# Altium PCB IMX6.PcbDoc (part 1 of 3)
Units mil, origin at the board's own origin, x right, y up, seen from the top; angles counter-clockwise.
Board outline 7950 x 5550 mil, 4 copper layers (Top Layer, GND, VCC, Bottom Layer), stack 30.634 mil thick; 238 components, 319 nets, 1015 pads, 404 vias.
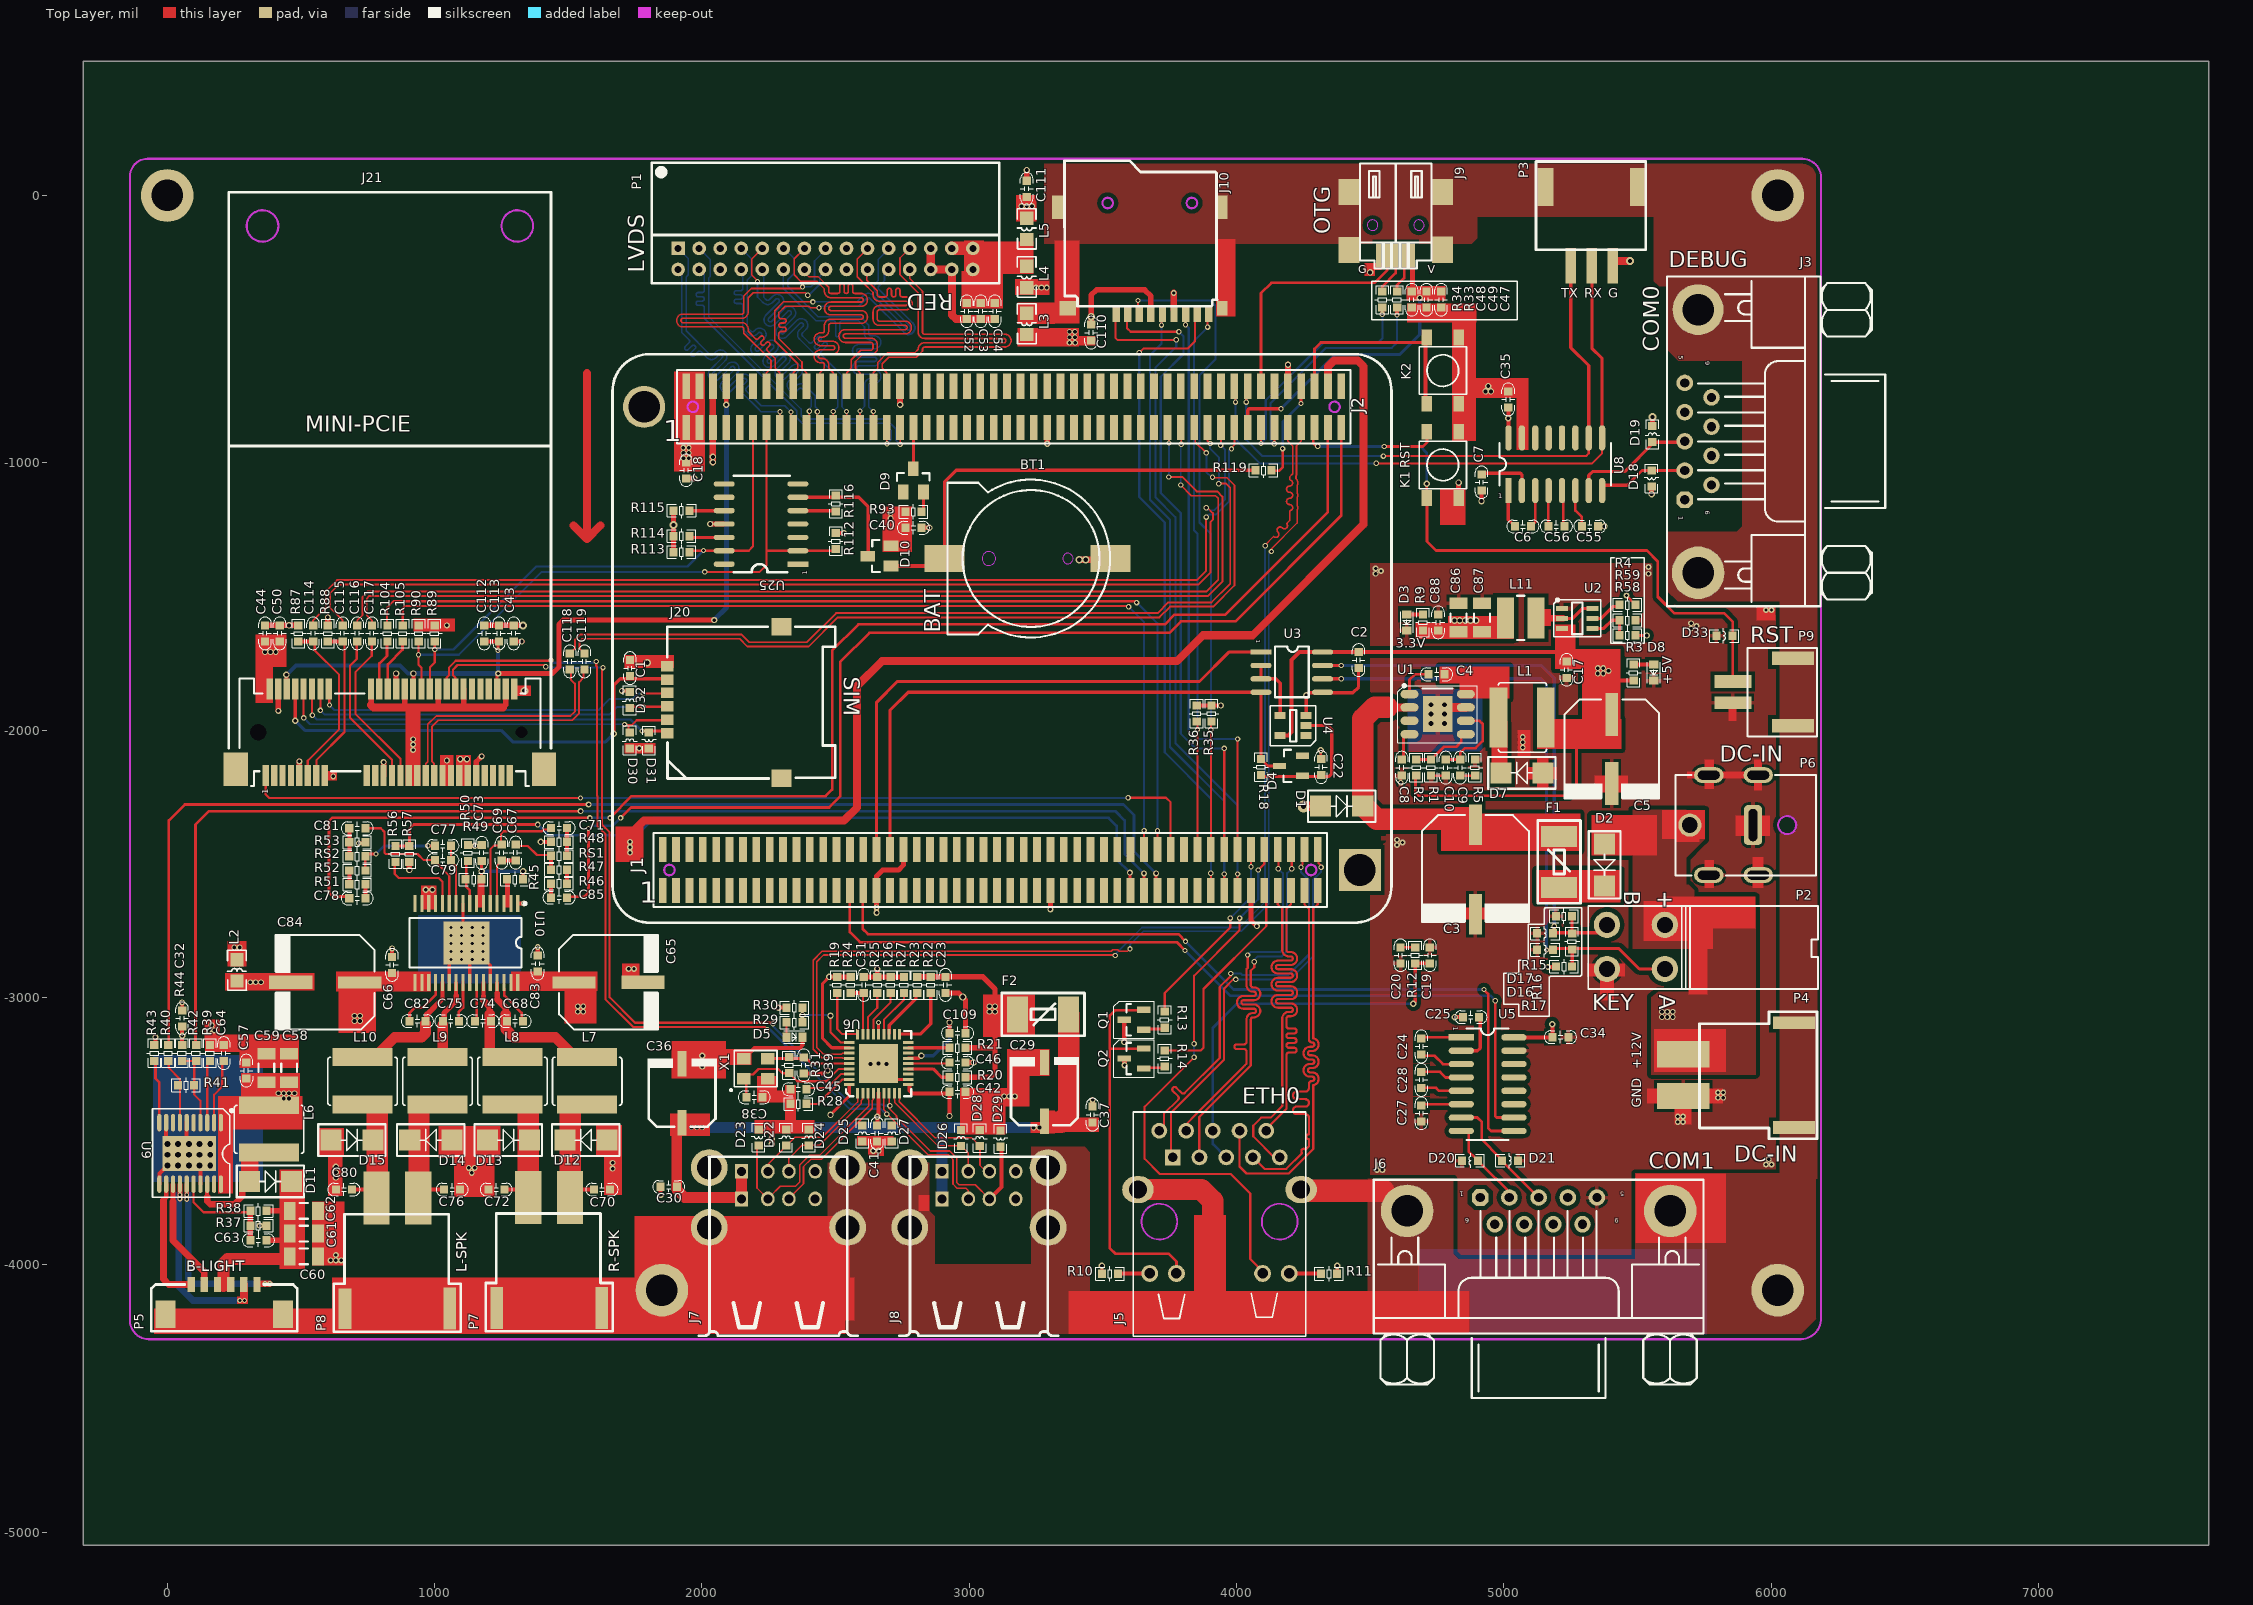
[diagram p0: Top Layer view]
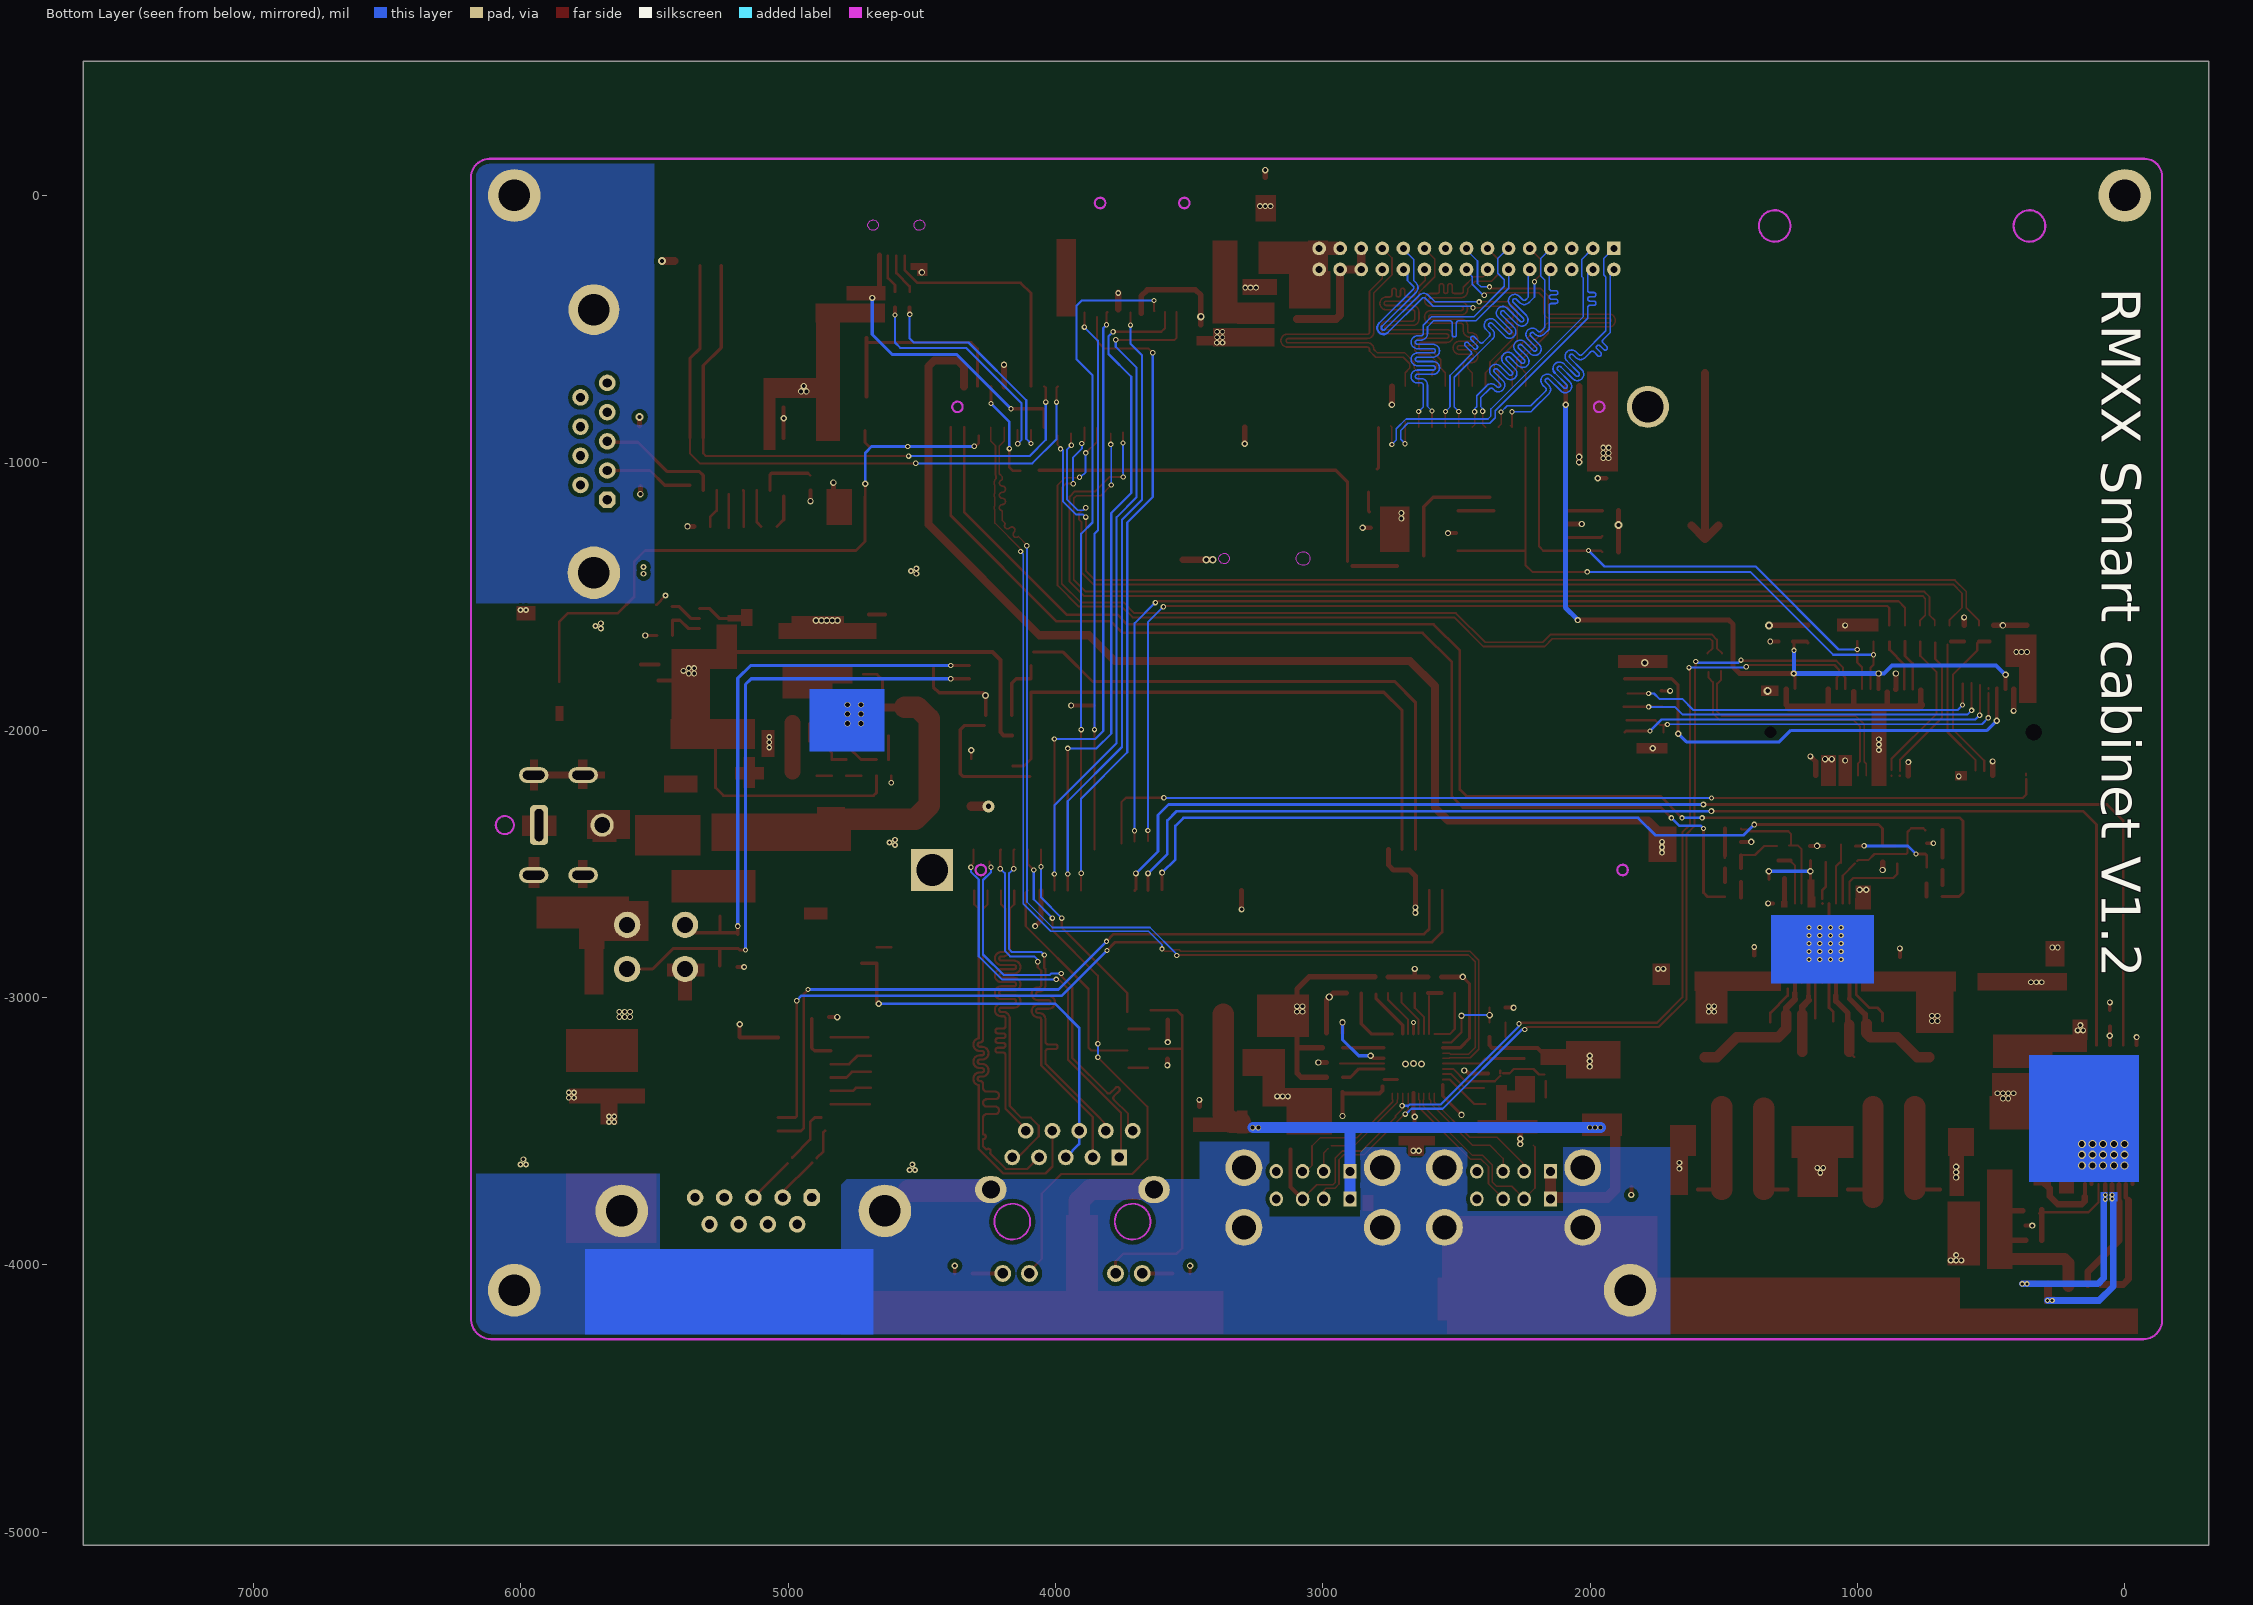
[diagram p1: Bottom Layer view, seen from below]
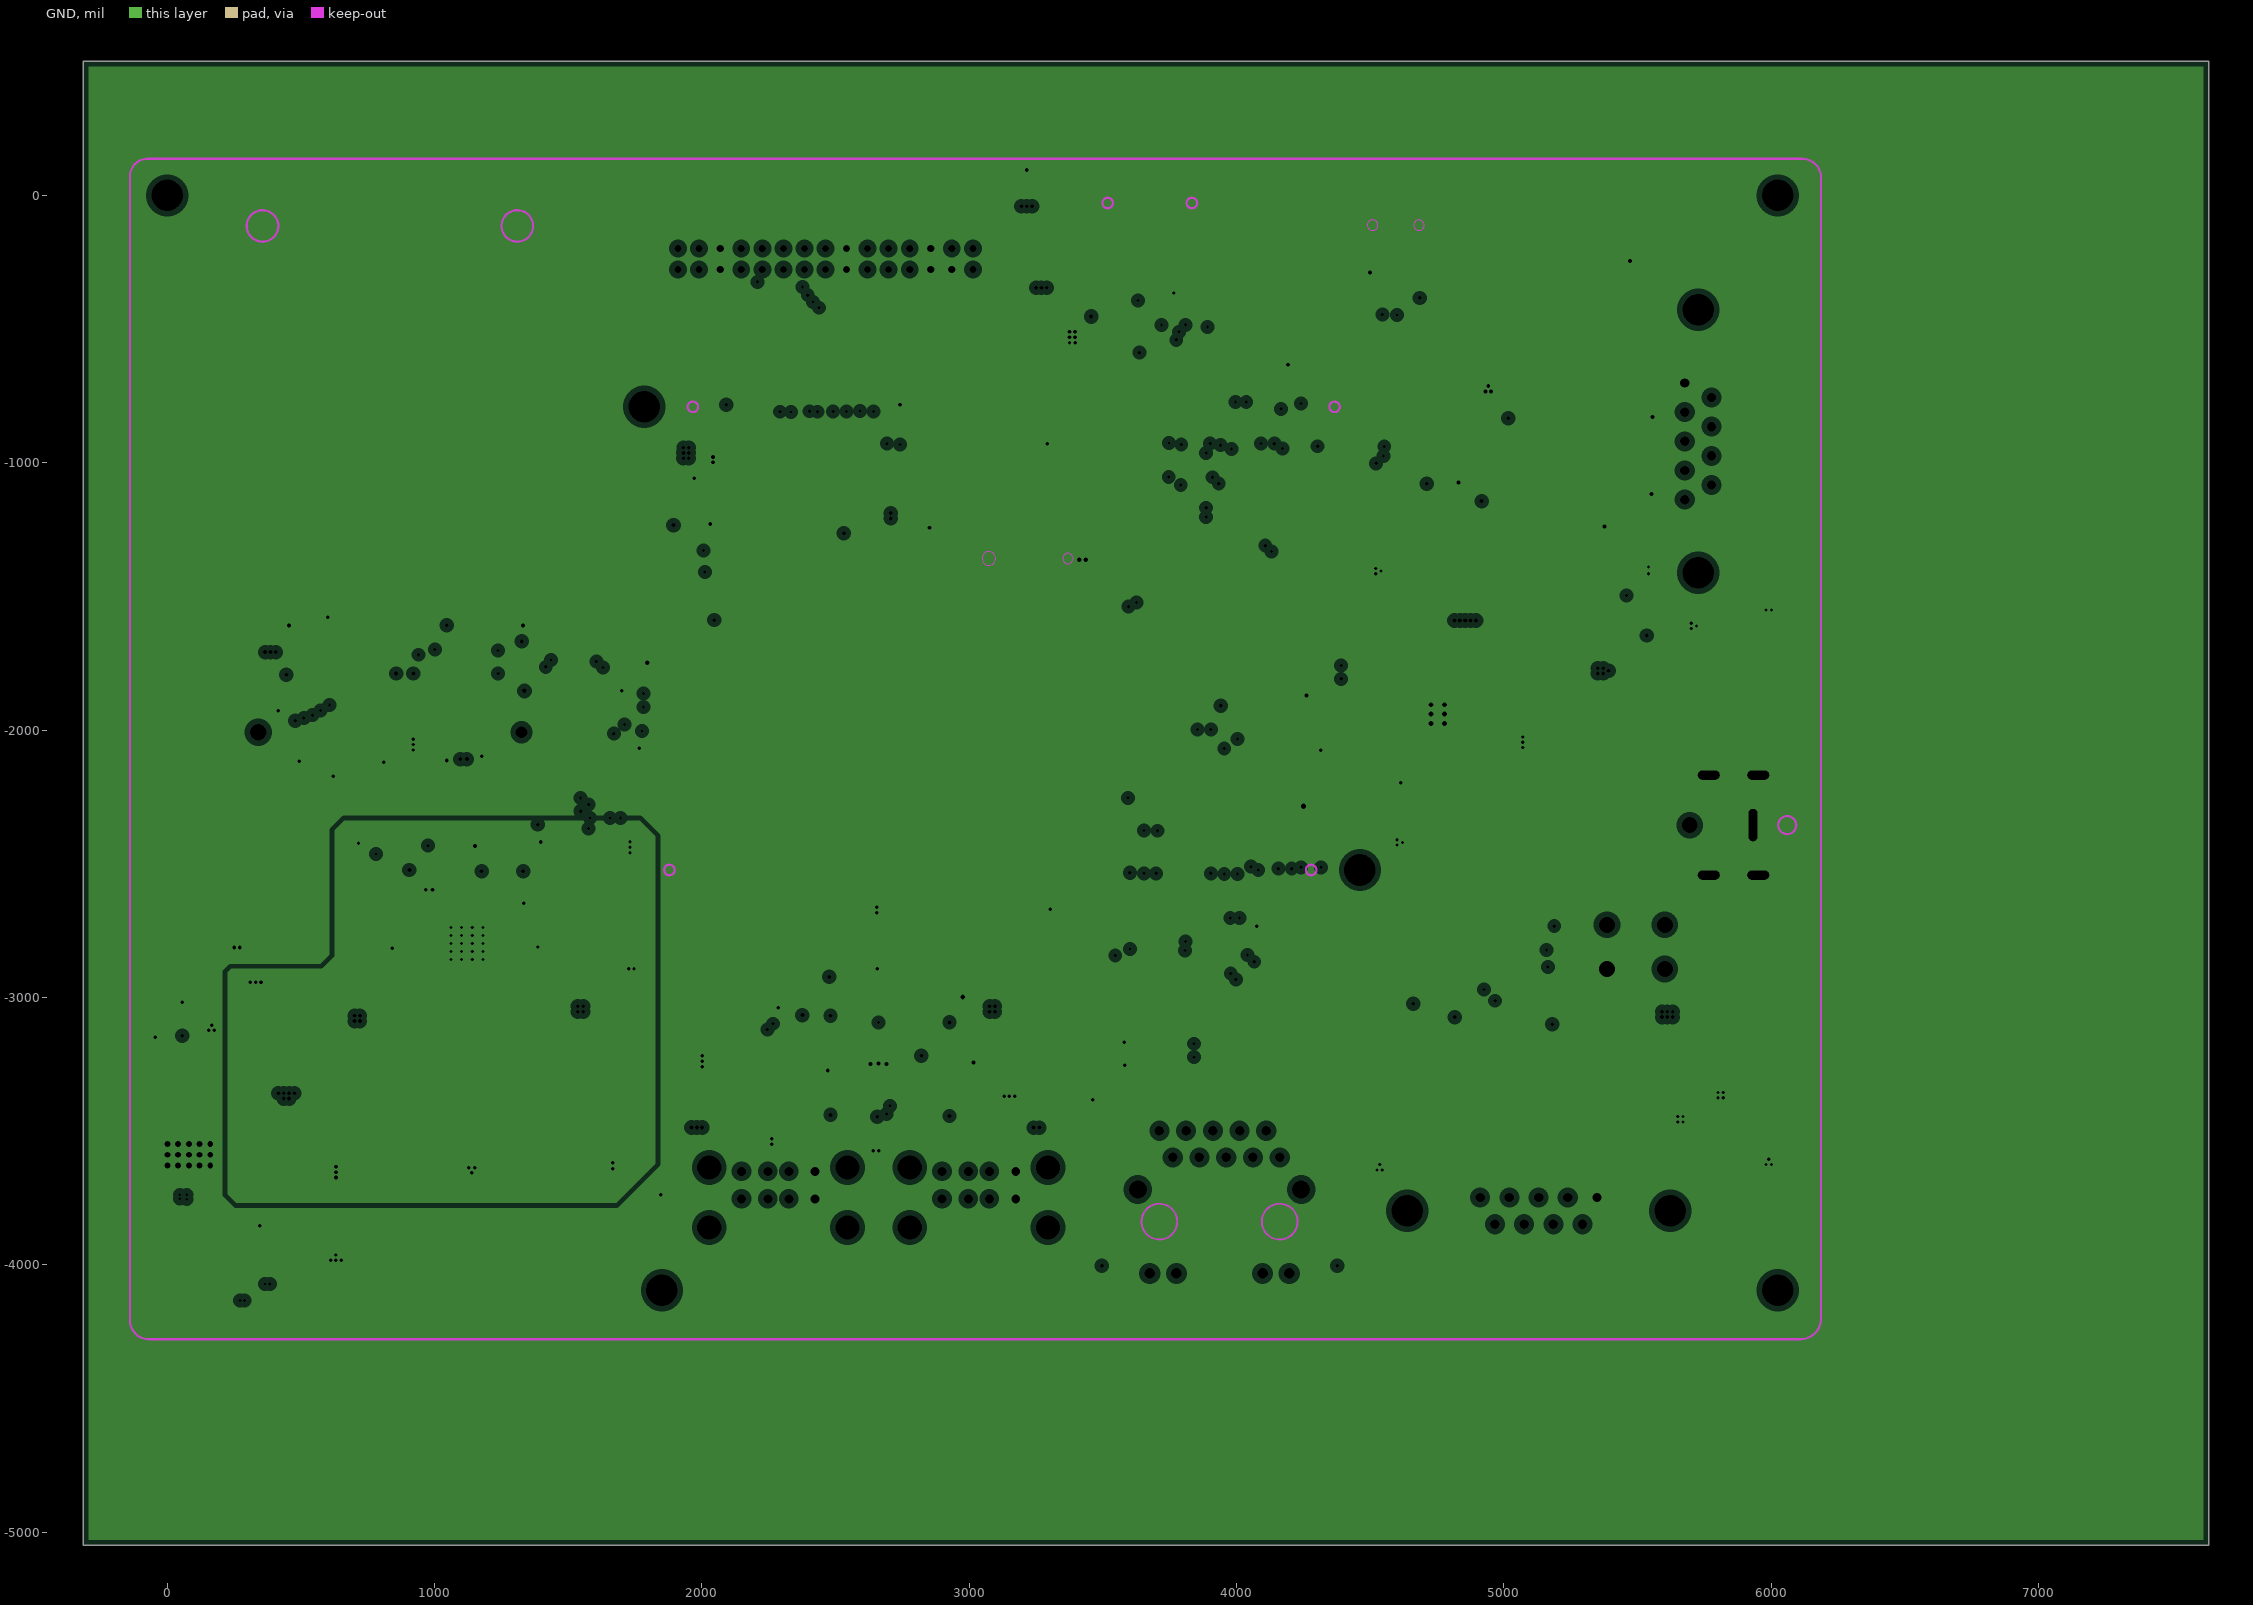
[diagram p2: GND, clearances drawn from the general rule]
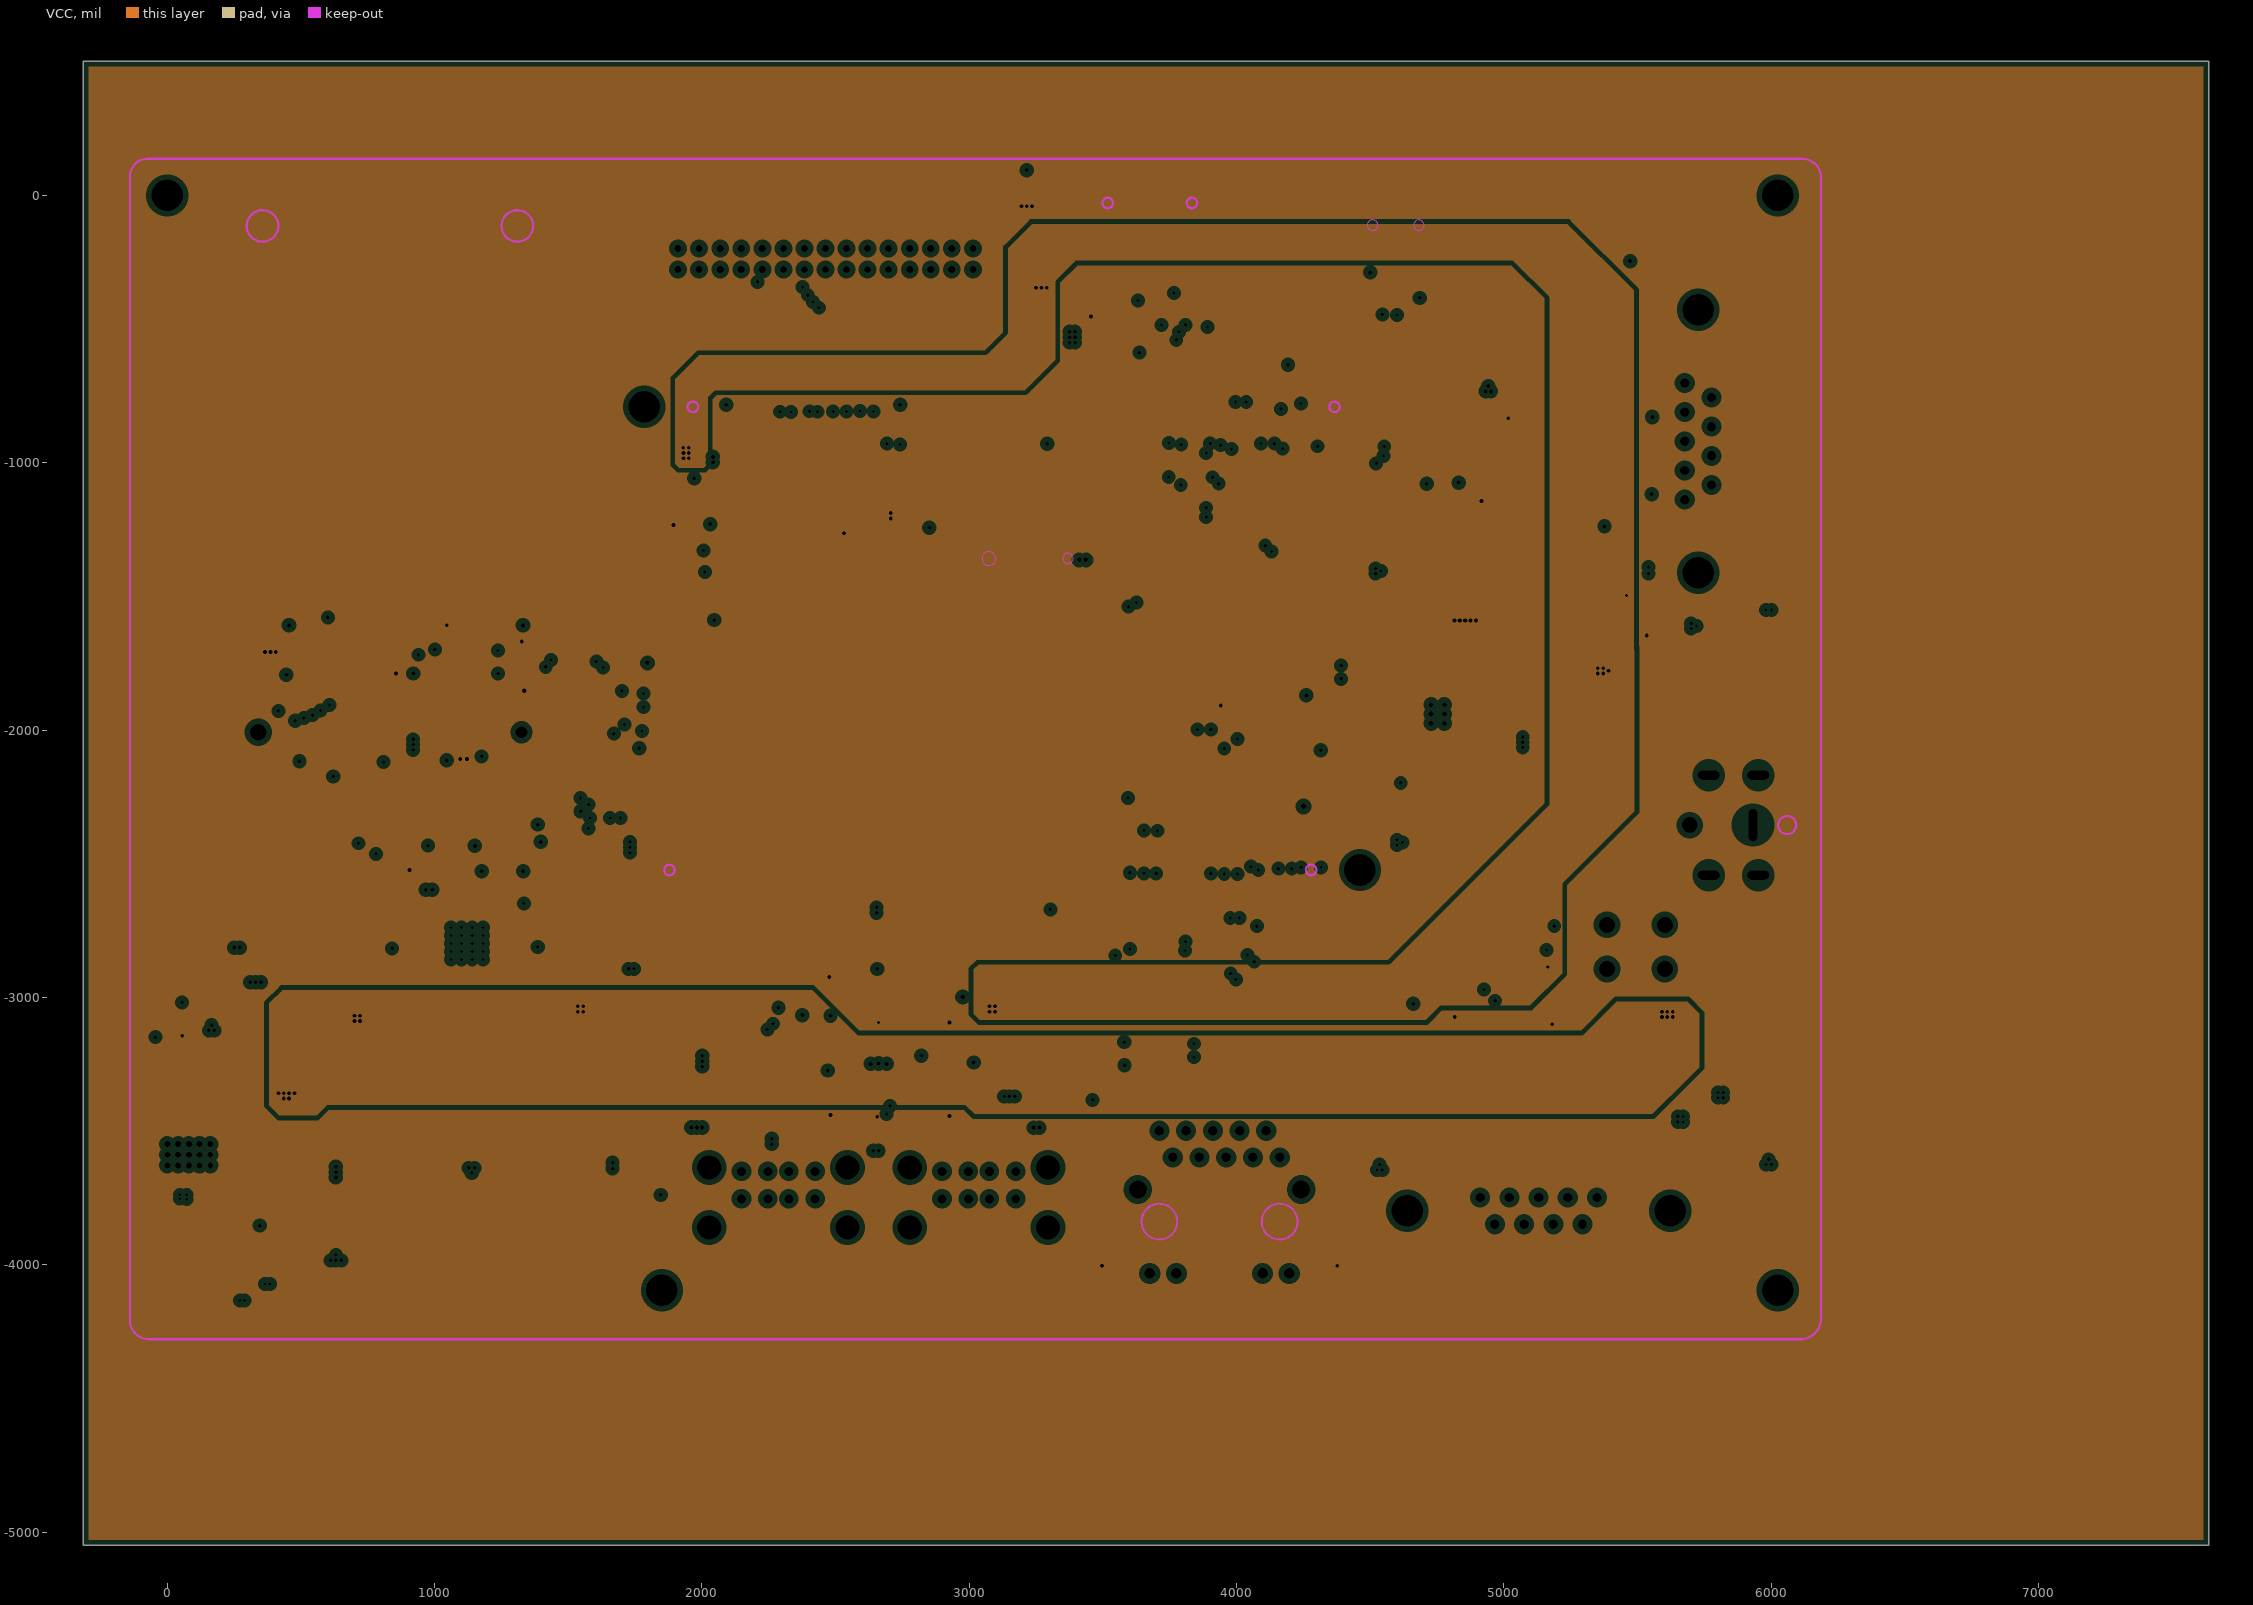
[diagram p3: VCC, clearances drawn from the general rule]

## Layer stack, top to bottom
Top Solder: solder mask 0.4, Solder Resist, Dk 3.5
Top Layer: signal copper 1.4
Dielectric1: core 10, FR-4, Dk 4.2
GND: plane copper 1.417
Dielectric5: prepreg 5, Dk 4.2
VCC: plane copper 1.417
Dielectric6: core 10, Dk 4.2
Bottom Layer: signal copper 1.4
Bottom Solder: solder mask 0.4, Solder Resist, Dk 3.5

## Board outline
-314,502 7636,502 7636,-5048 -314,-5048

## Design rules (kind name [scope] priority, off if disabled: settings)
Clearance [All] p1 off: gap=10 except(15: Arc-Poly Track-Poly SMDPad-Poly THPad-Poly Via-Poly Fill-Poly Poly-Poly Poly-Region Poly-Text)
ComponentClearance [All] p1 off: gap=0 collisioncheckmode=3 verticalgap=0 showdistances=FALSE
DiffPairsRouting [All] p1: maxlimit=10 minlimit=8 mostfreqgap=8 toplayer_minwidth=15 toplayer_maxwidth=15 toplayer_prefwidth=15 bottomlayer_minwidth=15 bottomlayer_maxwidth=15 bottomlayer_prefwidth=15 maxuncoupledlength=500
FabricationTestpoint [(IsPad And (OnTopLayer Or OnBottomLayer))] p1: side=3 testpointundercomponent=TRUE minsize=40 maxsize=100 preferedsize=60 minholesize=0 maxholesize=40 preferedholesize=32 testpointgrid=1 allowsidetop=TRUE allowsidebottom=TRUE usegrid=TRUE gridtolerance=0.01
HoleSize [All] p1: absolutevalues=TRUE maxlimit=300 minlimit=1 maxpercent=80.000 minpercent=20.000
PlaneClearance [All] p1: clearance=20
PlaneConnect [All] p1: planeconnectstyle=Direct reliefexpansion=20 reliefentries=4 reliefconductorwidth=12 reliefairgap=10
PolygonConnect [All] p1: connectstyle=Direct reliefconductorwidth=15 reliefentries=4 polygonreliefangle="90 Angle" airgapwidth=10
RoutingVias [All] p1: holewidth=12 width=20 viastyle="Through Hole" minholewidth=8 minwidth=16 maxholewidth=200 maxwidth=300
SolderMaskExpansion [All] p1: expansion=4
Width [All] p1: maxlimit=200 minlimit=6 preferedwidth=10 minimp=50.000000 maximp=50.000000 favimp=50.000000
24 further rules are at their usual default settings.

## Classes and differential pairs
component class 10.LVDS: C52 C53 C54 C57 C58 C59 C60 C61 C62 C63 C64 D11 L4 L5 L6 P1 P5 R37 R38 R39 R40 R41 R42 R43 R44 U9
component class 12.WTD&RTC: BT1 D9 D10 D33 K1 K2 P9 R93 R112 R113 R114 R115 R116 R119 U25
component class 8.SATA&TFCARD: C40 C50 J10 R35 R36
component class 5.USB: C29 C30 C31 C32 C34 C35 C36 C37 C38 C39 C41 C42 C43 C44 C45 C46 C47 C48 C49 D5 D22 D23 D24 D25 D26 D27 D28 D29 F2 J7 J8 J9 R19 R20 R21 R22 R23 R24 R25 R26 R27 R28 R29 R30 R31 R33 R34 U6 X1
component class 3.UART: C6 C7 C22 C23 C24 C25 C27 C28 C55 C56 D4 D16 D17 D18 D19 D20 D21 J3 J6 P3 R15 R16 R17 R18 U3 U4 U5 U8
component class 2.ETH: C19 C20 J5 Q1 Q2 R10 R11 R12 R13 R14
component class 1.POWER: C3 C4 C5 C8 C9 C10 C17 C18 C86 C87 C88 D1 D2 D3 D7 D8 F1 L1 L2 L3 L11 P6 R1 R2 R3 R4 R5 R9 R58 R59 U1 U2
component class 11.EX-MODULE: C65 C66 C67 C68 C69 C70 C71 C72 C73 C74 C75 C76 C77 C78 C79 C80 C81 C82 C83 C84 C85 D12 D13 D14 D15 L7 L8 L9 L10 P7 P8 R45 R46 R47 R48 R49 R50 R51 R52 R53 R56 R57 RS1 RS2 U10
component class 0.CONNECTOR: C2 J1 J2
component class 7.MINIPCIE: C1 C109 C110 C111 C112 C113 C114 C115 C116 C117 C118 C119 D30 D31 D32 J20 J21 R87 R88 R89 R90 R104 R105
differential pair USB_PORT4: +USB_PORT4_P -USB_PORT4_N
differential pair USB_PORT3: +USB_PORT3_P -USB_PORT3_N
differential pair USB_PORT2: +USB_PORT2_P -USB_PORT2_N
differential pair USB_PORT1: +USB_PORT1_P -USB_PORT1_N
differential pair USB_OTG_D: +USB_OTG_D_P -USB_OTG_D_N
differential pair USB_H1_D: +USB_H1_D_P -USB_H1_D_N
differential pair TRX3: +TRX3_P -TRX3_N
differential pair TRX2: +TRX2_P -TRX2_N
differential pair TRX1: +TRX1_P -TRX1_N
differential pair TRX0: +TRX0_P -TRX0_N
differential pair LVDS1_TX3: +LVDS1_TX3_P -LVDS1_TX3_N
differential pair LVDS1_TX2: +LVDS1_TX2_P -LVDS1_TX2_N
differential pair LVDS1_TX1: +LVDS1_TX1_P -LVDS1_TX1_N
differential pair LVDS1_TX0: +LVDS1_TX0_P -LVDS1_TX0_N
differential pair LVDS1_CLK: +LVDS1_CLK_P -LVDS1_CLK_N
differential pair LVDS0_TX3: +LVDS0_TX3_P -LVDS0_TX3_N
differential pair LVDS0_TX2: +LVDS0_TX2_P -LVDS0_TX2_N
differential pair LVDS0_TX1: +LVDS0_TX1_P -LVDS0_TX1_N
differential pair LVDS0_TX0: +LVDS0_TX0_P -LVDS0_TX0_N
differential pair LVDS0_CLK: +LVDS0_CLK_P -LVDS0_CLK_N
differential pair CLK1O: +CLK1O_P -CLK1O_N
differential pair CLK1: +CLK1_P -CLK1_N
differential pair PCIE_RXO: +PCIE_RXO_P -PCIE_RXO_N
differential pair PCIE_RX: +PCIE_RX_P -PCIE_RX_N
differential pair PCIE_TXO: +PCIE_TXO_P -PCIE_TXO_N
differential pair PCIE_TX: +PCIE_TX_P -PCIE_TX_N

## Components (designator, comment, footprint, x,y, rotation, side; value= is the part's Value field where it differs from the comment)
BT1 "" CR1220 3231,-1358 r180 top
C1 "0.1uF" 0603C 1731,-1768 r180 top
C2 "0.1uF" 0603C 4456,-1738 r0 top
C3 "Cap Pol3" C10-SMD 4893,-2518 r270 top
C4 "Cap" 0603C 4748,-1791 r270 top
C5 "Cap Pol3" C8X10-SMD 5403,-2070 r270 top
C6 "0.1uF" 0603C 5071,-1238 r90 top
C7 "0.1uF" 0603C 4916,-1073 r0 top
C8 "Cap" 0603C 4618,-2140 r0 top
C9 "Cap" 0603C 4836,-2140 r180 top
C10 "Cap" 0603C 4782,-2140 r180 top
C17 "10uF" 0603C 5234,-1774 r0 top
C18 "0.1uF" 0603C 1941,-1028 r0 top
C19 "0.1uF" 0603C 4723,-2842 r180 top
C20 "NC(1uF)" 0603C 4613,-2842 r180 top
C22 "1nF" 0603C 4316,-2138 r0 top
C23 "0.1uF" 0603C 2911,-2953 r0 top
C24 "0.1uF" 0603C 4691,-3183 r0 top
C25 "0.1uF" 0603C 4876,-3073 r270 top
C27 "0.1uF" 0603C 4691,-3433 r0 top
C28 "0.1uF" 0603C 4691,-3308 r0 top
C29 "220uF/16V" C6.3x5.4-SMD 3281,-3353 r90 top
C30 "0.1uF" 0603C 1876,-3708 r90 top
C31 "0.1uF" 0603C 2606,-2953 r0 top
C32 "4.7uF" 0603C 56,-3078 r0 top
C34 "4.7uF" 0603C 5211,-3148 r270 top
C35 "0.1uF" 0603C 5016,-763 r0 top
C36 "220uF/16V" C6.3x5.4-SMD 1926,-3358 r90 top
C37 "0.1uF" 0603C 3461,-3438 r0 top
C38 "18pF" 0603C 2196,-3373 r270 top
C39 "18pF" 0603C 2381,-3253.52 r180 top
C40 "0.1uF" 0603C 2791,-1243 r270 top
C41 "0.1uF" 0603C 2655,-3508 r180 top
C42 "0.1uF" 0603C 2956,-3353 r270 top
C43 "0.1uF" 0603C 1296,-1638 r0 top
C44 "4.7uF" 0603C 366,-1638 r0 top
C45 "1uF" 0603C 2361,-3343 r90 top
C46 "1uF" 0603C 2956,-3243 r270 top
C47 "0.1uF" 0603C 4765,-390 r180 top
C48 "22uF" 0603C 4655,-390 r180 top
C49 "22uF" 0603C 4710,-390 r180 top
C50 "22uF" 0603C 421,-1638 r0 top
C52 "0.1uF" 0603C 2991,-433 r0 top
C53 "22uF" 0603C 3043,-433 r180 top
C54 "22uF" 0603C 3096,-433 r180 top
C55 "0.1uF" 0603C 5321,-1238 r90 top
C56 "0.1uF" 0603C 5196,-1238 r90 top
C57 "Cap" 0603C 296,-3273 r180 top
C58 "Cap" C1206 456,-3263 r270 top
C59 "Cap" C1206 371,-3263 r270 top
C60 "Cap" C1206 511,-3968 r180 top
C61 "Cap" C1206 511,-3883 r180 top
C62 "Cap" C1206 511,-3798 r180 top
C63 "Cap" 0603C 341,-3908 r90 top
C64 "Cap" 0603C 212,-3208 r0 top
C65 "470U/35V" C8X10-SMD 1651,-2943 r0 top
C66 "224" 0603C 841,-2878 r180 top
C67 "105" 0603C 1303,-2458 r0 top
C68 "224" 0603C 1301,-3088 r270 top
C69 "301" 0603C 1251,-2458 r180 top
C70 "105" 0603C 1626,-3718 r270 top
C71 "105" 0603C 1466,-2366 r270 top
C72 "105" 0603C 1231,-3718 r270 top
C73 "105" 0603C 1177,-2459 r0 top
C74 "224" 0603C 1181,-3088 r90 top
C75 "224" 0603C 1061,-3088 r270 top
C76 "105" 0603C 1066,-3718 r270 top
C77 "105" 0603C 1031,-2433 r90 top
C78 "106" 0603C 711,-2629 r90 top
C79 "301" 0603C 1031,-2486 r270 top
C80 "105" 0603C 661,-3718 r270 top
C81 "105" 0603C 711,-2367 r90 top
C82 "224" 0603C 936,-3088 r90 top
C83 "224" 0603C 1386,-2873 r180 top
C84 "470U/35V" C8X10-SMD 591,-2943 r180 top
C85 "106" 0603C 1466,-2626 r270 top
C86 "47uF" C1206 4830,-1579 r90 top
C87 "47uF" C1206 4918,-1579 r90 top
C88 "0.1uF" 0603C 4754,-1597 r180 top
C109 "0.1uF" 0603C 2956,-3133 r90 top
C110 "0.1uF" 0603C 3456,-513 r0 top
C111 "22uF" 0603C 3215,25 r180 top
C112 "0.1uF" 0603C 1186,-1638 r180 top
C113 "0.1uF" 0603C 1241,-1638 r180 top
C114 "0.1uF" 0603C 546,-1638 r0 top
C115 "0.1uF" 0603C 656,-1638 r0 top
C116 "0.1uF" 0603C 711,-1638 r0 top
C117 "0.1uF" 0603C 766,-1638 r0 top
C118 "0.1uF" 0603C 1506,-1743 r0 top
C119 "0.1uF" 0603C 1561,-1743 r0 top
D1 "SMAJ16A" SMA 4393,-2284 r0 top
D2 "SS54" SMA 5376,-2504 r270 top
D3 "发光二极管" 0603D 4637,-1597 r180 top
D4 "BAT54C" SOT-23#1 4261,-2093 r0 top
D5 "发光二极管" 0603D 2346,-3148 r270 top
D7 "SS54" SMA 5067,-2160 r180 top
D8 "发光二极管" 0603D 5560,-1785 r180 top
D9 "BAT54C" SOT-23#2 2831,-1123 r270 top
D10 "BAT54C" SOT-23#2 2721,-1308 r0 top
D11 "SS210" SMA 386,-3688 r0 top
D12 "M7" SMA 1566,-3533 r180 top
D13 "M7" SMA 1276,-3533 r0 top
D14 "M7" SMA 986,-3533 r180 top
D15 "M7" SMA 691,-3533 r0 top
D16 "ESD" 0603L 5154,-2761 r270 top
D17 "ESD" 0603L 5154,-2822 r270 top
D18 "ESD" 0603L 5551,-1058 r180 top
D19 "ESD" 0603L 5556,-893 r0 top
D20 "ESD" 0603L 4873,-3609 r90 top
D21 "ESD" 0603L 5023,-3611 r270 top
D22 "ESD" 0603L 2316,-3523 r0 top
D23 "ESD" 0603L 2211,-3523 r180 top
D24 "ESD" 0603L 2401,-3523 r0 top
D25 "ESD" 0603L 2601,-3508 r0 top
D26 "ESD" 0603L 2970,-3525 r0 top
D27 "ESD" 0603L 2711,-3508 r0 top
D28 "ESD" 0603L 3040,-3525 r0 top
D29 "ESD" 0603L 3116,-3528 r180 top
D30 "ESD" 0603L 1731,-2038 r0 top
D31 "ESD" 0603L 1801,-2038 r180 top
D32 "ESD" 0603L 1731,-1888 r0 top
D33 "ESD" 0603L 5824,-1648 r270 top
F1 "Fuse Thermal" 1812F 5206,-2588 r90 top
F2 "1A  FUSE" 1812F 3181,-3063 r0 top
J1 "CON50X2" IDC50X2-1.27MM_SMT 3078.52,-2523 r0 top locked
J2 "CON50X2" IDC50X2-1.27MM_SMT 3166.31,-790.72 r0 top locked
J3 "DB9" DB-9/M#1 5676,-1138 r180 top
J5 "48F-01GY2DPL2NL" RJ45C-48F-01GY2DPL2NL 3711,-3498 r0 top locked
J6 "DB9" DB-9/M#2 4911,-3748 r90 top
J7 "USB-D" USB-D 2286,-3748 r180 top
J8 "USB-D" USB-D 3036,-3748 r180 top
J9 "USB_AB" "MINI USB B" 4595,-225 r180 top locked
J10 "TF-CARD" TF-CARD 3607,-370 r270 top
J20 "MICRO-SIM" MACRO-SIM 2298,-1613 r270 top
J21 "Mini PCI Express" MINI-PCIE 833,-2008 r0 top locked
K1 "KEY" SS-SPB-4.5 4771,-1008 r270 top
K2 "KEY" SS-SPB-4.5 4771,-655 r270 top
L1 "Inductor" L-6045 4979,-1952 r0 top
L2 "电感" 0805L 261,-2858 r0 top
L3 "电感" 0805L 3215,-520 r180 top
L4 "NC" 0805L 3215,-345 r180 top
L5 "电感" 0805L 3215,-165 r180 top
L6 "Inductor" L-6045 381,-3403 r270 top
L7 "10UH" L-6045 1571,-3223 r270 top
L8 "10UH" L-6045 1291,-3223 r270 top
L9 "10UH" L-6045 1011,-3223 r270 top
L10 "10UH" L-6045 731,-3223 r270 top
L11 "3.3uH" L4030 5063,-1580 r0 top
P1 "Header 15X2" 2.0-15P*2 1911,-198 r0 top locked
P2 "POWIN" 5569 5385,-2728 r270 top
P3 "TTL" HY2.0-3P 5250,-263 r0 top
P4 "POW-IN" VH3.96-2P-SMT#1 5671,-3368 r90 top
P5 "Header 6" 1.25MM-6P 336,-4073 r0 top
P6 "POW-IN" DC-5525 5951,-2168 r270 top
P7 "CON2" VH3.96-2P-SMT#1 1351,-3748 r0 top
P8 "CON2" VH3.96-2P-SMT#2 783,-3750 r0 top
P9 "RST" PH2.0-2-SMT 5856,-1818 r270 top
Q1 "9012" SOT-23-PMOS 3616,-3083 r180 top
Q2 "9012" SOT-23-PMOS 3616,-3228 r180 top
R1 "Res Semi" 0603R 4727,-2140 r180 top
R2 "Res Semi" 0603R 4672,-2140 r0 top
R3 "Res1" 0603R 5485,-1785 r180 top
R4 "10K" 0603R 5462,-1531 r270 top
R5 "Res Semi" 0603R 4892,-2140 r0 top
R9 "1K" 0603R 4697,-1597 r0 top
R10 "1K" 0603R 3526,-4033 r270 top
R11 "1K" 0603R 4346,-4033 r90 top
R12 "NC(0)" 0603R 4668,-2842 r0 top
R13 "4.7K" 0603R 3731,-3083 r180 top
R14 "4.7K" 0603R 3731,-3228 r180 top
R15 "1K" 0603R 5224,-2696 r270 top
R16 "120(NC)" 0603R 5255,-2790 r180 top
R17 "1K" 0603R 5225,-2884 r90 top
R18 "22K" 0603R 4091,-2138 r180 top
R19 "0R" 0603R 2506,-2953 r180 top
R20 "10K" 0603R 2956,-3298 r270 top
R21 "10K" 0603R 2956,-3188 r270 top
R22 "10K" 0603R 2856,-2953 r0 top
R23 "10K" 0603R 2806,-2953 r0 top
R24 "100K" 0603R 2556,-2953 r0 top
R25 "100K" 0603R 2656,-2953 r180 top
R26 "100K" 0603R 2706,-2953 r180 top
R27 "100K" 0603R 2756,-2953 r180 top
R28 "12K 1%" 0603R 2361,-3398 r90 top
R29 "1K" 0603R 2346,-3093 r90 top
R30 "100K" 0603R 2346,-3038 r270 top
R31 "1M" 0603R 2326,-3253 r180 top
R33 "33R" 0603R 4600,-390 r0 top
R34 "33R" 0603R 4545,-390 r0 top
R35 "10K" 0603R 3906,-1938 r180 top
R36 "10K" 0603R 3851,-1938 r180 top
R37 "Res1" 0603R 341,-3853 r270 top
R38 "Res1" 0603R 341,-3798 r90 top
R39 "Res1" 0603R 160,-3208 r0 top
R40 "Res1" 0603R 4,-3208 r180 top
R41 "Res1" 0603R 71,-3328 r90 top
R42 "Res1" 0603R 108,-3208 r180 top
R43 "Res1" 0603R -48,-3208 r180 top
R44 "Res1" 0603R 56,-3208 r180 top
R45 "20K" 0603R 1301,-2558 r270 top
R46 "330R" 0603R 1466,-2574 r90 top
R47 "4K7" 0603R 1466,-2522 r90 top
R48 "4K7" 0603R 1466,-2418 r270 top
R49 "100K" 0603R 1146,-2558 r90 top
R50 "20K" 0603R 1125,-2459 r180 top
R51 "330R" 0603R 711,-2577 r270 top
R52 "4K7" 0603R 711,-2525 r270 top
R53 "4K7" 0603R 711,-2419 r90 top
R56 "2K" 0603R 854,-2463 r0 top
R57 "10K" 0603R 906,-2463 r180 top
R58 "4.3K" 0603R 5462,-1645 r270 top
R59 "680R" 0603R 5462,-1589 r270 top
R87 "49.9R  1%" 0603R 491,-1638 r0 top
R88 "49.9R  1%" 0603R 601,-1638 r0 top
R89 "4.7K(NC)" 0603R 1000,-1638 r0 top
R90 "4.7K(NC)" 0603R 941,-1638 r0 top
R93 "10K" 0603R 2791,-1183 r270 top
R104 "0R(NC)" 0603R 824,-1638 r0 top
R105 "0R(NC)" 0603R 881,-1638 r0 top
R112 "4.7K(NC)" 0603R 2501,-1293 r180 top
R113 "4.7K(NC)" 0603R 1924,-1334 r270 top
R114 "10K" 0603R 1924,-1274 r270 top
R115 "10K" 0603R 1924,-1179 r270 top
R116 "0(NC)" 0603R 2501,-1153 r180 top
R119 "0(NC)" 0603R 4101,-1028 r270 top
RS1 "NC" 0603R 1466,-2470 r90 top
RS2 "NC" 0603R 711,-2472 r270 top
U1 "TPS54331" SOP8-POW 4752,-1940 r0 top
U2 "TPS562201" SOT23-6-DC 5274,-1582 r0 top
U3 "MAX485ESA" SOP8-1.27 4091,-1708 r0 top
U4 "SN74LVC1G04" SOT23-5N 4211,-1983 r180 top
U5 "SP3232EEN" SOIC16-1.27 4936,-3298 r0 top
U6 "USB2514BI" QFN-36 2661,-3248 r90 top
U8 "SP3232EEN" SOIC16-1.27 5166,-1008 r90 top
U9 "TPS61194" HTTSOP-20 201,-3468 r270 top
U10 "TPA3116" HTSSOP-32 1311,-2648 r180 top
U25 "RX8025-SA" SOP14-1.27 2359,-1379 r180 top
X1 "24M" OSC4-3225 2156,-3303 r0 top

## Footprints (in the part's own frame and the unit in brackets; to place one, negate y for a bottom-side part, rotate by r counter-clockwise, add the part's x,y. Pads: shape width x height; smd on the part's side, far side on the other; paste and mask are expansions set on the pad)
1.25MM-6P [mm]
  rect 1.9x2.6 smd: 0(-8.7,-2.835) 0(2.45,-2.835)
  rect 0.7x1.4 smd: 1(-6.25,0) 2(-5,0) 3(-3.75,0) 4(-2.5,0) 5(-1.25,0) 6(0,0)
  silkscreen extent -10.03,-4.44 3.81,0
2.0-15P*2 [mm]
  rect 1.301x1.301 hole 0.68: 1(0,0)
  round 1.301 hole 0.68: 2(0,-2) 3(2,0) 4(2,-2) 5(4,0) 6(4,-2) 7(6,0) 8(6,-2) 9(8,0) 10(8,-2) 11(10,0) 12(10,-2) 13(12,0) 14(12,-2) 15(14,0) 16(14,-2) 17(16,0) 18(16,-2) 19(18,0) 20(18,-2) 21(20,0) 22(20,-2) 23(22,0) 24(22,-2) 25(24,0) 26(24,-2) 27(26,0) 28(26,-2) 29(28,0) 30(28,-2)
  silkscreen extent -2.5,-3.3 30.5,8.15
0603C [mil]
  rect 31.5x30 smd: 1(0,30) 2(0,-30)
  silkscreen extent -24,-60 24,60
0603D [mil]
  rect 35.43x30 smd: A(0,-30) K(0,30)
  silkscreen extent -24,-40 24,39
0603L [mil]
  rect 31.5x30 smd: 1(-0.91,-29.91) 2(-0.91,30.09)
  silkscreen extent -28,-54 27,54
0603R [mil]
  rect 31.5x30 smd: 1(0,30) 2(0,-30)
  silkscreen extent -28,-53 28,53
0805L [mil]
  rect 50x50 smd: 1(0,0) 2(0,-80)
  silkscreen extent -35,-115 36,35
1812F [mm]
  rect 2x3.4 smd: 1(0,0) 2(4.85,0)
  silkscreen extent -1.5,-2.03 6.35,2.03
5569 [mm]
  round 2.5 hole 1.524: 1(0,0) 2(4.2,0) 3(4.2,5.5) 4(0,5.5)
  silkscreen extent -1.78,-1.78 6.1,20.07
C6.3x5.4-SMD [mm]
  rect 2.4x0.85 smd: 1(-2.794,0) 2(2.794,0)
  silkscreen extent -3.17,-3.3 3.3,3.3, body extent -3.24,-3.18 3.24,3.18, height 3.5
C8X10-SMD [mm]
  rect 4.1x1.148 smd: 1(-3.277,0)
  rect 4.1x1.25 smd: 2(3.277,0)
  silkscreen extent -4.7,-4.5 4.7,4.5, body extent -4.65,-4.25 4.65,4.25, height 10.5
C10-SMD [mm]
  rect 3.85x1.25 smd: 1(-4.191,0) 2(4.318,0)
  silkscreen extent -5.08,-5.08 5.08,5.08
C1206 [mm] "Chip Capacitor, Body 3.2x1.6mm, IPC High Density"
  rect 1.1x1.7 smd: 1(-1.35,0) 2(1.35,0)
  silkscreen extent -0.4,-0.75 0.4,0.75, body extent -1.7,-0.9 1.7,0.9, height 1.3
CR1220 [mm]
  rect 3.8x2.6 smd: 1(8.23,0) 2(-7.57,0)
  Keep-Out Layer circle w0.1: c-3.5,0 r0.5
  Keep-Out Layer circle w0.1: c4,0 r0.65
  silkscreen extent -7.5,-7.5 7.94,7.5
DB-9/M#1 [mil]
  oct 62x62 hole 35: 1(0,0)
  round 62 hole 35: 2(0,-109.17) 3(0,-218.33) 4(0,-327.5) 5(0,-436.67) 6(-100,-55) 7(-100,-164.17) 8(-100,-273.33) 9(-100,-382.5)
  round 190 hole 118.33: BO1(-50,-710.83)
  round 196.67 hole 118.33: BO2(-50,273.33)
  silkscreen extent -750,-835 67,398
DB-9/M#2 [mil]
  oct 62x62 hole 35: 1(0,0)
  round 62 hole 35: 2(0,-109.17) 3(0,-218.33) 4(0,-327.5) 5(0,-436.67) 6(-100,-55) 7(-100,-164.17) 8(-100,-273.33) 9(-100,-382.5)
  round 196.67 hole 118.33: BO1(-50,-710.83) BO2(-50,273.33)
  silkscreen extent -750,-835 67,398
DC-5525 [mm]
  oval 1.5x2.8 hole 0.85 slot 2.06 at 90 deg: 1(0,0) 1(0,-4.7) 1(9.5,-4.7) 1(9.5,0)
  rrect50% 3.8x1.75 hole 0.83 slot 3.05 at 0 deg: 1(4.75,-0.5)
  round 2.2 hole 1.5: 2(4.75,-6.5)
  Keep-Out Layer circle w0.2: c4.75,2.75 r0.86
  silkscreen extent 0,-7.87 9.53,5.5
HTSSOP-32 [mm]
  rect 0.3x1.6 smd: 1(0,0) 2(0.65,0) 3(1.3,0) 4(1.95,0) 5(2.6,0) 6(3.25,0) 7(3.9,0) 8(4.55,0) 9(5.2,0) 10(5.85,0) 11(6.5,0) 12(7.15,0) 13(7.8,0) 14(8.45,0) 15(9.1,0) 16(9.75,0) 17(9.75,7.5) 18(9.1,7.5) 19(8.45,7.5) 20(7.8,7.5) 21(7.15,7.5) 22(6.5,7.5) 23(5.85,7.5) 24(5.2,7.5) 25(4.55,7.5) 26(3.9,7.5) 27(3.25,7.5) 28(2.6,7.5) 29(1.95,7.5) 30(1.3,7.5) 31(0.65,7.5) 32(0,7.5)
  rect 4.36x4.11 smd: 33(4.875,3.75)
  silkscreen extent -0.83,-0.12 10.29,6.1
HTTSOP-20 [mm]
  oval 1.65x0.4 smd: 1(0,0) 2(0,-0.65) 3(0,-1.3) 4(0,-1.95) 5(0,-2.6) 6(0,-3.25) 7(0,-3.9) 8(0,-4.55) 9(0,-5.2) 10(0,-5.85) 11(5.842,-5.85) 12(5.842,-5.2) 13(5.842,-4.55) 14(5.842,-3.9) 15(5.842,-3.25) 16(5.842,-2.6) 17(5.842,-1.95) 18(5.842,-1.3) 19(5.842,-0.65) 20(5.842,0)
  rect 3.3x5.08 smd: 21(2.921,-3)
  silkscreen extent -1.32,-6.5 7.07,1.14, body extent 0.64,-6.2 5.08,0.28, height 2.65
HY2.0-3P [mm]
  rect 1.5x3.6 smd: 0(-2.413,7.493) 0(6.369,7.493)
  rect 1x3.4 smd: 1(0,0) 2(2,0) 3(4,0)
  silkscreen extent -3.3,1.52 7.11,9.91
IDC50X2-1.27MM_SMT [mm]
  rect 0.74x2.4 smd: 1(-31.115,-1.95) 2(-31.115,1.95) 3(-29.845,-1.95) 4(-29.845,1.95) 5(-28.575,-1.95) 6(-28.575,1.95) 7(-27.305,-1.95) 8(-27.305,1.95) 9(-26.035,-1.95) 10(-26.035,1.95) 11(-24.765,-1.95) 12(-24.765,1.95) 13(-23.495,-1.95) 14(-23.495,1.95) 15(-22.225,-1.95) 16(-22.225,1.95) 17(-20.955,-1.95) 18(-20.955,1.95) 19(-19.685,-1.95) 20(-19.685,1.95) 21(-18.415,-1.95) 22(-18.415,1.95) 23(-17.145,-1.95) 24(-17.145,1.95) 25(-15.875,-1.95) 26(-15.875,1.95) 27(-14.605,-1.95) 28(-14.605,1.95) 29(-13.335,-1.95) 30(-13.335,1.95) 31(-12.065,-1.95) 32(-12.065,1.95) 33(-10.795,-1.95) 34(-10.795,1.95) 35(-9.525,-1.95) 36(-9.525,1.95) 37(-8.255,-1.95) 38(-8.255,1.95) 39(-6.985,-1.95) 40(-6.985,1.95) 41(-5.715,-1.95) 42(-5.715,1.95) 43(-4.445,-1.95) 44(-4.445,1.95) 45(-3.175,-1.95) 46(-3.175,1.95) 47(-1.905,-1.95) 48(-1.905,1.95) 49(-0.635,-1.95) 50(-0.635,1.95) 51(0.635,-1.95) 52(0.635,1.95) 53(1.905,-1.95) 54(1.905,1.95) 55(3.175,-1.95) 56(3.175,1.95) 57(4.445,-1.95) 58(4.445,1.95) 59(5.715,-1.95) 60(5.715,1.95) 61(6.985,-1.95) 62(6.985,1.95) 63(8.255,-1.95) 64(8.255,1.95) 65(9.525,-1.95) 66(9.525,1.95) 67(10.795,-1.95) 68(10.795,1.95) 69(12.065,-1.95) 70(12.065,1.95) 71(13.335,-1.95) 72(13.335,1.95) 73(14.605,-1.95) 74(14.605,1.95) 75(15.875,-1.95) 76(15.875,1.95) 77(17.145,-1.95) 78(17.145,1.95) 79(18.415,-1.95) 80(18.415,1.95) 81(19.685,-1.95) 82(19.685,1.95) 83(20.955,-1.95) 84(20.955,1.95) 85(22.225,-1.95) 86(22.225,1.95) 87(23.495,-1.95) 88(23.495,1.95) 89(24.765,-1.95) 90(24.765,1.95) 91(26.035,-1.95) 92(26.035,1.95) 93(27.305,-1.95) 94(27.305,1.95) 95(28.575,-1.95) 96(28.575,1.95) 97(29.845,-1.95) 98(29.845,1.95) 99(31.115,-1.95) 100(31.115,1.95)
  Keep-Out Layer circle w0.203: c30.48,0 r0.5
  Keep-Out Layer circle w0.203: c-30.48,0 r0.5
  silkscreen extent -32,-3.5 32,3.5
L4030 [mm]
  rect 1.6x3.9 smd: 1(-1.45,0) 2(1.45,0)
  silkscreen extent -0.35,-2.1 0.35,2.1
L-6045 [mm]
  rect 1.7x5.7 smd: 1(0,0) 2(4.5,0)
  silkscreen extent 0,-3.3 4.57,3.3
MACRO-SIM [mm]
  rect 1x1.2 smd: 1(3.75,-10.86) 2(5.02,-10.86) 3(6.29,-10.86) 4(7.56,-10.86) 5(8.83,-10.86) 6(10.1,-10.86)
  rect 1.7x1.9 smd: ""(0,-0.01) ""(14.4,-0.01)
  silkscreen extent 0,-10.86 14.43,5.1
"MINI USB B" [mm]
  rect 0.5x2.3 smd: 1(-1.6,0) 2(-0.8,0) 3(0,0) 4(0.8,0) 5(1.6,0)
  rect 2x2.5 smd: 6(4.45,-6.038) 7(4.45,-0.538) 8(-4.45,-0.554) 9(-4.45,-6.038)
  Keep-Out Layer circle w0.1: c-2.2,-2.893 r0.5
  Keep-Out Layer circle w0.1: c2.2,-2.893 r0.5
  silkscreen extent -3.4,-8.74 3.4,1.22, body extent -5.32,-8.77 5.38,0.43, height 3.95
MINI-PCIE [mm]
  rect 0.6x2 smd: 1(-11.8,-4.1) 2(-11.4,4.1) 3(-11,-4.1) 4(-10.6,4.1) 5(-10.2,-4.1) 6(-9.8,4.1) 7(-9.4,-4.1) 8(-9,4.1) 9(-8.6,-4.1) 10(-8.2,4.1) 11(-7.8,-4.1) 12(-7.4,4.1) 13(-7,-4.1) 14(-6.6,4.1) 15(-6.2,-4.1) 16(-5.8,4.1) 17(-2.2,-4.1) 18(-1.8,4.1) 19(-1.4,-4.1) 20(-1,4.1) 21(-0.6,-4.1) 22(-0.2,4.1) 23(0.2,-4.1) 24(0.6,4.1) 25(1,-4.1) 26(1.4,4.1) 27(1.8,-4.1) 28(2.2,4.1) 29(2.6,-4.1) 30(3,4.1) 31(3.4,-4.1) 32(3.8,4.1) 33(4.2,-4.1) 34(4.6,4.1) 35(5,-4.1) 36(5.4,4.1) 37(5.8,-4.1) 38(6.2,4.1) 39(6.6,-4.1) 40(7,4.1) 41(7.4,-4.1) 42(7.8,4.1) 43(8.2,-4.1) 44(8.6,4.1) 45(9,-4.1) 46(9.4,4.1) 47(9.8,-4.1) 48(10.2,4.1) 49(10.6,-4.1) 50(11,4.1) 51(11.4,-4.1) 52(11.8,4.1)
  rect 2.3x3.2 smd: 53(-14.65,-3.5) 54(14.65,-3.5)
  rrect70% 0x0 hole 1.6: 55(-12.5,0)
  rrect70% 0x0 hole 1.1: 56(12.5,0)
  Keep-Out Layer circle w0.203: c12.103,48.103 r1.5
  Keep-Out Layer circle w0.203: c-12.097,48.103 r1.5
  silkscreen extent -15.3,-5.1 15.3,51.3
OSC4-3225 [mm]
  rect 1.3x1.1 smd: 1(0,0) 2(2.3,0) 3(2.3,1.9) 4(0,1.9)
  silkscreen extent -1.28,-1.19 3.17,2.67
PH2.0-2-SMT [mm]
  rect 1.3x4 smd: 0(-2.2,5.715) 0(4.191,5.715)
  rect 1.2x3.5 smd: 1(0,0) 2(2,0)
  silkscreen extent -3.18,1.4 5.21,8
QFN-36 [mm]
  rect 1x0.28 smd: 1(-2.777,2) 2(-2.777,1.5) 3(-2.777,1) 4(-2.777,0.5) 5(-2.777,0) 6(-2.777,-0.5) 7(-2.777,-1) 8(-2.777,-1.5) 9(-2.777,-2) 19(2.823,-2) 20(2.823,-1.5) 21(2.823,-1) 22(2.823,-0.5) 23(2.823,0) 24(2.823,0.5) 25(2.823,1) 26(2.823,1.5) 27(2.823,2)
  rect 0.28x1 smd: 10(-1.977,-2.8) 11(-1.477,-2.8) 12(-0.977,-2.8) 13(-0.477,-2.8) 14(0.023,-2.8) 15(0.523,-2.8) 16(1.023,-2.8) 17(1.523,-2.8) 18(2.023,-2.8) 28(2.023,2.8) 29(1.523,2.8) 30(1.023,2.8) 31(0.523,2.8) 32(0.023,2.8) 33(-0.477,2.8) 34(-0.977,2.8) 35(-1.477,2.8) 36(-1.977,2.8)
  rect 3.7x3.7 smd: 37(0.023,0)
  silkscreen extent -3.08,-3.1 3.12,3.1
RJ45C-48F-01GY2DPL2NL [mm]
  round 1.5 hole 0.9: 1(0,0) 3(2.54,0) 4(3.81,-2.54) 5(5.08,0) 6(6.35,-2.54) 7(7.62,0) 8(8.89,-2.54) 9(10.16,0) 10(11.43,-2.54)
  rect 1.5x1.5 hole 0.9: 2(1.27,-2.54)
  round 1.6 hole 1: 11(-0.915,-13.565) 12(1.625,-13.565) 13(9.805,-13.565) 14(12.345,-13.565)
  oval 3x2.54 hole 1.7: 15(-2.035,-5.59) 16(13.465,-5.59)
  Keep-Out Layer circle w0.178: c11.43,-8.64 r1.7
  Keep-Out Layer circle w0.178: c0,-8.64 r1.7
  silkscreen extent -2.48,-19.54 13.92,1.77
SMA [mm]
  rect 2x2 smd: A(-2,0) K(2,0)
  silkscreen extent -3.2,-1.5 3.2,1.5
SOIC16-1.27 [mm]
  rect 2.4x0.6 smd: 1(-2.432,3.787)
  oval 2.4x0.6 smd: 2(-2.432,2.517) 3(-2.432,1.247) 4(-2.432,-0.023) 5(-2.432,-1.293) 6(-2.432,-2.563) 7(-2.432,-3.833) 8(-2.432,-5.103) 9(2.568,-5.103) 10(2.568,-3.833) 11(2.568,-2.563) 12(2.568,-1.293) 13(2.568,-0.023) 14(2.568,1.247) 15(2.568,2.517) 16(2.568,3.787)
  silkscreen extent -1.93,-5.96 2.07,4.64
SOP8-1.27 [mm]
  rect 2x0.5 smd: 1(0,0)
  oval 2x0.5 smd: 2(0,-1.27) 3(0,-2.54) 4(0,-3.81) 5(5.85,-3.81) 6(5.85,-2.54) 7(5.85,-1.27) 8(5.85,0)
  silkscreen extent 1.35,-4.29 4.54,0.53
SOP8-POW [mm]
  oval 1.7x0.8 smd: 1(-2.675,1.905) 2(-2.675,0.635) 3(-2.675,-0.635) 4(-2.675,-1.905) 5(2.675,-1.905) 6(2.675,-0.635) 7(2.675,0.635) 8(2.675,1.905)
  rect 2.8x3.4 smd: 9(0,0)
  silkscreen extent -3.78,-2.7 3.77,2.82
SOP14-1.27 [mm]
  rect 2x0.5 smd: 1(0,0)
  oval 2x0.5 smd: 2(0,-1.27) 3(0,-2.54) 4(0,-3.81) 5(0,-5.08) 6(0,-6.35) 7(0,-7.62) 8(7,-7.62) 9(7,-6.35) 10(7,-5.08) 11(7,-3.81) 12(7,-2.54) 13(7,-1.27) 14(7,0)
  silkscreen extent 0.76,-8.38 6.1,0.76
SOT23-5N [mm]
  rect 1.05x0.65 smd: 1(-1.225,0.95) 2(-1.225,0) 3(-1.225,-0.95) 4(1.225,-0.95) 5(1.225,0.95)
  silkscreen extent -2.16,-1.91 2.16,1.91, body extent -0.87,-1.5 0.88,1.5, height 1.1
SOT23-6-DC [mm] "SOT23, 6-Leads, Body 3.0x3.7mm (max), Pitch 0.95mm, IPC Medium Density"
  rect 1.1x0.5 smd: 1(-1.45,0.95) 2(-1.45,0) 3(-1.45,-0.95) 4(1.45,-0.95) 5(1.45,0) 6(1.45,0.95)
  silkscreen extent -2.25,-1.75 2.25,1.88, body extent -0.87,-1.5 0.87,1.5, height 1.1
SOT-23#1 [mil] "SOT23, 3-Leads, Body 3.0x2.6mm (max), Pitch 0.95mm, IPC Medium Density"
  rect 49x24 smd: 1(-14.05,-78.06) 2(-14.05,-2.06) 3(-101.05,-41.06)
  silkscreen extent -85,-101 -56,20
SOT-23#2 [mil]
  rect 55x40 smd: 1(-14.05,-78.06) 2(-14.05,-2.06) 3(-101.05,-41.06)
  silkscreen extent -85,-101 -56,20
SOT-23-PMOS [mm]
  rect 1.25x0.6 smd: 1(-0.925,0.95) 2(-0.925,-0.95) 3(0.925,0)
  silkscreen extent -1.91,-1.78 1.91,1.78, body extent -0.7,-1.5 0.7,1.5, height 1.1
SS-SPB-4.5 [mm]
  rect 1.5x1 smd: 1(-3.15,1.5) 2(3.15,1.5) 3(3.15,-1.5) 4(-3.15,-1.5)
  silkscreen extent -2.25,-2.25 2.25,2.25
TF-CARD [mm]
  rect 1.6x0.7 smd: 1(1.82,-1.466) 2(1.82,-0.366) 3(1.82,0.734) 4(1.82,1.834) 5(1.82,2.934) 6(1.82,4.034) 7(1.82,5.134) 8(1.82,6.234) 9(1.82,7.334)
  rect 1.4x1 smd: 10(1.32,8.634)
  rect 2.2x1.2 smd: 11(-8.28,8.534) 12(-8.28,-6.966)
  rect 1.4x1.6 smd: 13(1.32,-6.066)
  Keep-Out Layer circle w0.203: c-8.68,5.734 r0.5
  Keep-Out Layer circle w0.203: c-8.68,-2.266 r0.5
  silkscreen extent -12.7,-6.37 1.12,8.13
USB-D [mm]
  rect 1.27x1.4 hole 0.85: 1(3.5,-2.49) 5(3.5,0.13)
  oval 1.27x1.4 hole 0.85: 2(1,-2.49) 3(-1,-2.49) 4(-3.5,-2.49) 6(1,0.13) 7(-1,0.13) 8(-3.5,0.13)
  round 3.5 hole 2.3: 9(6.57,-2.84) 10(-6.57,-2.84) 11(6.57,2.84) 12(-6.57,2.84)
  silkscreen extent -7.55,-3.88 7.55,13.12
VH3.96-2P-SMT#1 [mm]
  rect 1.2x4 smd: 0(-3,-10.5) 0(6.96,-10.5)
  rect 2.5x5 smd: 1(3.96,0) 2(0,0)
  silkscreen extent -4.06,-12.7 8,-1.52
VH3.96-2P-SMT#2 [mm]
  rect 1.25x3.85 smd: 0(-3,-10.5)
  rect 1.2x4 smd: 0(6.96,-10.5)
  rect 2.5x5 smd: 1(3.96,0) 2(0,0)
  silkscreen extent -4.06,-12.7 8,-1.52

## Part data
BT1: library part 电池
C1 C2 C6 C7 C17 C18 C19 C20 C22 C23 C24 C25 C27 C28 C30 C31 C32 C34 C35 C37 C38 C39 C40 C41 C42 C43 C44 C45 C46 C47 C48 C49 C50 C52 C53 C54 C55 C56 C86 C87 C88 C109 C110 C111 C112 C113 C114 C115 C116 C117 C118 C119: library part 电容, "电容"
C3 C5: "Polarized Capacitor (Surface Mount)"
C4 C8 C9 C10 C57 C58 C59 C60 C61 C62 C63 C64: "Capacitor"
C29 C36: library part 直插电解电容, "直插电解电容"
C65 C84: library part ELECTRO
C66 C67 C68 C69 C70 C71 C72 C73 C74 C75 C76 C77 C78 C79 C80 C81 C82 C83 C85: library part CAP
D1 D2 D7 D11 D12 D13 D14 D15: library part SS24
D4 D9 D10: "SCHOTTKY DIODE"
D16 D17 D18 D19 D20 D21 D22 D23 D24 D25 D26 D27 D28 D29 D30 D31 D32 D33: library part 电感
F1: "Thermal Fuse"
F2: library part FUSE, "贴片自恢复保险丝"
J1 J2: "ASTRON B2B Connector"
J7 J8: "USB DOUBLE PORTS"
J9: "小USB插痤"
J21: library part MINIPCIE, "MPC24-52K3311"
K1 K2: library part 按键, "按键"
L4: library part 电感, "电感"
L7 L8 L9 L10: library part INCLUDE
L11: library part 功率电感
P1: "Header, 15-Pin, Dual row"
P2: library part "Header 2X2", "Header, 2-Pin, Dual row"
P3: library part "Header 3", "Header, 3-Pin"
P4 P6 P9: library part "Header 2", "Header, 2-Pin"
P5: "Header, 6-Pin"
R1 R2 R5: "Semiconductor Resistor"
R3 R37 R38 R39 R40 R41 R42 R43 R44: "Resistor"
R4 R9 R10 R11 R12 R13 R14 R15 R16 R17 R18 R19 R20 R21 R22 R23 R24 R25 R26 R27 R28 R29 R30 R31 R33 R34 R35 R36 R58 R59 R87 R88 R89 R90 R93 R104 R105 R112 R113 R114 R115 R116 R119: library part 电阻, "电阻"
R45 R46 R47 R48 R49 R50 R51 R52 R53 R56 R57 RS1 RS2: library part RES
U5 U8: library part MAX232ESE
U6: library part USB2514, "USB2514Bi"
U10: library part TPA3116D2
U25: "I2C interface RTC with crystal built-in"
X1: library part 表贴晶体, "4PIN表贴晶体"

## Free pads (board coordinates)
  round 196.85 hole 118.11: 0(0,0) 0(1850.39,-4094.49) 0(6023.62,-4094.49) 0(6023.62,0)
  round 157.48 hole 118.11: 0(1783.83,-790.72)
  rect 157.48x157.48 hole 118.11: 0(4461,-2523)

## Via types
v1: diameter 20, hole 12, Top Layer to Bottom Layer, 138 vias
v2: diameter 22, hole 14, Top Layer to Bottom Layer, 54 vias
v3: diameter 24, hole 14, Top Layer to Bottom Layer, 53 vias
v4: diameter 22, hole 12, Top Layer to Bottom Layer, 39 vias
v5: diameter 23, hole 13, Top Layer to Bottom Layer, 38 vias
v6: diameter 22, hole 13, Top Layer to Bottom Layer, 21 vias
v7: diameter 30, hole 22, Top Layer to Bottom Layer, tented top, 15 vias
v8: diameter 22, hole 18, Top Layer to Bottom Layer, 6 vias
v9: diameter 25, hole 16, Top Layer to Bottom Layer, 5 vias
v10: diameter 24, hole 13, Top Layer to Bottom Layer, 5 vias
v11: diameter 20, hole 15, Top Layer to Bottom Layer, 5 vias
v12: diameter 30, hole 15, Top Layer to Bottom Layer, 4 vias
v13: diameter 18, hole 10, Top Layer to Bottom Layer, 4 vias
v14: diameter 20, hole 14, Top Layer to Bottom Layer, 4 vias
v15: diameter 28, hole 16, Top Layer to Bottom Layer, 3 vias
v16: diameter 26, hole 15, Top Layer to Bottom Layer, 3 vias
v17: diameter 45, hole 20, Top Layer to Bottom Layer, 1 vias
v18: diameter 28, hole 17, Top Layer to Bottom Layer, 1 vias
v19: diameter 25, hole 15, Top Layer to Bottom Layer, 1 vias
v20: diameter 28, hole 15, Top Layer to Bottom Layer, 1 vias
v21: diameter 18, hole 12, Top Layer to Bottom Layer, 1 vias
v22: diameter 30, hole 16, Top Layer to Bottom Layer, 1 vias
v23: diameter 25, hole 14, Top Layer to Bottom Layer, 1 vias

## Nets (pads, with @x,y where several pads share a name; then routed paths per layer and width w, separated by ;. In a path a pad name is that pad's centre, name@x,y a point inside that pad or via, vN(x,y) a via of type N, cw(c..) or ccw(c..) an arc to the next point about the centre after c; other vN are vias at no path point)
485_A: D17.2 P2.3 R16.1 R17.2 U3.6 | length 2362.5
  Top Layer w12: U3.6@4321.31,-1808 v1(4391,-1808) ; v1(5159,-2822) D17.2@5181,-2822 ; D17.2@5185,-2817 5430,-2817 5506.35,-2893.35 P2.3@5601.54,-2893.35 ; R17.2@5255,-2881 R16.1@5255,-2820
  Bottom Layer w12: v1(4391,-1808) 5138,-1808 5159,-1829 v1@5159,-2814
485_B: D16.2 P2.1 R15.1 R16.2 U3.7 | length 2123
  Top Layer w12: U3.7@4321.31,-1758 v1(4391,-1758) ; D16.2@5188,-2764 D16.2@5188,-2758 ; v4(5188,-2733) D16.2@5188,-2758 ; R16.2@5254,-2759 R16.2@5254,-2758 ; R15.1@5254,-2696 R16.2@5254,-2758 ; P2.1@5391,-2728 5361,-2758 R16.2@5254,-2758 ; D16.2@5188,-2758 R16.2@5254,-2758
  Bottom Layer w12: v1(4391,-1758) 5140,-1758 5188,-1806 v4(5188,-2733)
485_DE1: U3.2 U3.3 U4.4 | length 249.5
  Top Layer w12: U3.2@4091,-1758 U3.3@4091,-1808 4146,-1808 4162.77,-1824.77 U4.4@4162.77,-1945.6
+12V: C3.1 D1.K F1.2 U1.2 | length 794.8
  Top Layer w80: 4563,-1914 4516,-1914 4472,-1958 4472,-2281 4524,-2333 4813,-2333
AU_MUTE: J1.71 R56.1 R57.2 | length 3082.1
  Top Layer w10: R56.1@856,-2433 R57.2@906,-2433 906,-2368 921,-2353 v6(1386,-2353) ; J1.71@3601,-2597.25 v6(3601,-2533)
  Bottom Layer w10: v6(1386,-2353) 1426,-2393 1756,-2393 1821,-2328 3521,-2328 3551,-2358 3551,-2483 v6(3601,-2533)
AUGND: C65.2 C66.2 C70.1 C72.2 C73.1 C76.1 C80.2 C83.2 C84.2 D12.A D13.A D14.A D15.A J2.98 L2.2 R48.2 R50.2 R53.2 U10.1 U10.9 U10.13 U10.14 U10.15 U10.22 U10.25 U10.28 U10.33 | length 4867.5
  Top Layer w12: v1(716,-2423) R53.2@741,-2423 ; U10.22@1055,-2940.18 U10.33@1055,-2860 ; U10.33@1106.28,-2754 U10.9@1106.28,-2648 ; U10.25@1131.87,-2943.28 U10.33@1131.87,-2868 ; U10.33@1198,-2868 1208.64,-2878.64 U10.28@1208.64,-2943.28
  Top Layer w15: C66.2@841,-2848 v6@841,-2818 ; R50.2@1126,-2433 C73.1@1177,-2433 ; U10.1@1316,-2648 v6@1333,-2648 ; C83.2@1386,-2843 v6@1386,-2812 ; v3@1398,-2418 R48.2@1436,-2418
  Top Layer w30: 1713,-2409 1784,-2338 2532,-2338 2580,-2290 2580,-1835 2673,-1742 3777,-1742 3874,-1645 4060,-1645 4475,-1230 4475,-639 4453,-617 4364,-617 4341.31,-639.69 J2.98@4341.31,-713.94
  other v1: 1061,-2858 1101,-2858 1141,-2858 1181,-2858 1061,-2828 1101,-2828 1141,-2828 1181,-2828 1061,-2798 1101,-2798 1141,-2798 1181,-2798 1061,-2768 1101,-2768 1141,-2768 1181,-2768 1061,-2738 1101,-2738 1141,-2738 1181,-2738
  other v2: 311,-2943 331,-2943 351,-2943
  other v3: 631,-3673 631,-3653 631,-3633 967,-2597 992,-2597 1151,-2433 1397,-2418
  other v5: 1726,-2893 1746,-2893 1731,-2458 1731,-2438 1731,-2418
  other v6: 1139,-3656 1666,-3640 1128,-3637 1150,-3637 1666,-3618 841,-2816 1386,-2811 1334,-2648
BAT_RTC: J2.94 R119.1 | length 378.2
  Top Layer w8: J2.94@4241,-714.26 J2.94@4241.31,-713.94
  Top Layer w10: R119.1@4132,-1030 4159,-1030 4172,-1017 v1(4172,-947) ; v1(4241,-778) J2.94@4241,-714.26
  Bottom Layer w10: v1@4172,-948 v1(4172,-947) 4172,-847 v1(4241,-778)
BG_EN: J1.73 R42.2 | length 4627
  Top Layer w10: R42.2@106,-3178 106,-2353 156,-2303 v6(1546,-2303) ; J1.73@3653.52,-2599.77 v6(3653.5,-2535.5)
  Bottom Layer w10: v6(1546,-2303) 3546,-2303 3581,-2338 3581,-2463 v6(3653.5,-2535.5)
BG_PWM: J1.75 R40.2 | length 4809.4
  Top Layer w10: R40.2@6,-3178 6,-2338 66,-2278 v6(1576,-2278) ; v6(3698.5,-2535.5) 3698.5,-2594.75 J1.75@3703.52,-2599.77
  Bottom Layer w10: v6(1576,-2278) 3576,-2278 3616,-2318 3616,-2453 v6(3698.5,-2535.5)
CAN1_RX: J2.12
CAN1_TX: J2.10
CAN2_RX: J2.7
CAN2_TX: J2.9
CCM_CLKO2: J2.36
CLK1_N: C114.1 J2.83 | length 4038.5
  Top Layer w7: C114.1@546,-1608 546,-1589 593,-1542 593,-1481.37 635.37,-1439 3851,-1439 3886,-1404 3886,-1222 v1(3886,-1203) ; v1@3975,-948 3976,-948 3992,-932 J2.83@3992,-897
  Bottom Layer w7: v1(3886,-1203) 3895.5,-1193.5 3922.63,-1193.5 3972,-1144.13 3972,-951 v1@3975,-948
  other v1: 3981,-948
CLK1_P: C115.1 J2.81 | length 4068.3
  Top Layer w7: C115.1@656,-1608 656,-1589 609,-1542 609,-1488 642,-1455 3857.63,-1455 3902,-1410.63 3902,-1222 3911,-1213 3911,-1188 3891,-1168 v1(3886,-1168) ; v1(3940,-934) 3941.31,-932.69 J2.81@3941.31,-891
  Bottom Layer w7: v1(3886,-1168) 3895.5,-1177.5 3916,-1177.5 3956,-1137.5 3956,-950 v1(3940,-934)
CLK1O_N: C114.2 J21.11 R87.2 | length 603.2
  Top Layer w8: J21.11@526,-2153 526,-2114 643,-1997 643,-1793 552,-1702 C114.2@552,-1675
  Top Layer w15: 507,-1668 C114.2@546,-1668
CLK1O_P: C115.2 J21.13 R88.2 | length 565.1
  Top Layer w8: J21.13@559,-2151 559,-2111 663,-2007 C115.2@663,-1679
  Top Layer w15: R88.2@601,-1668 C115.2@651,-1668
CSI0_HSYNCH: J2.37
CSI0_PIXCLK: J2.38
CSI_CLK0_N: J2.61
CSI_CLK0_P: J2.63
CSI_D0_N: J2.71
CSI_D0_P: J2.69
CSI_D1_N: J2.67
CSI_D1_P: J2.65
D_RXD: D18.1 J3.2 U8.8 | length 331.9
  Top Layer w12: U8.8@5367,-1084 5461,-1084 5516.17,-1028.83 J3.2@5676,-1028.83
D_TXD: D19.1 J3.3 U8.7 | length 462.2
  Top Layer w12: U8.7@5316.91,-1103.76 5316.91,-1047.09 5331,-1033 5451,-1033 5561,-923 J3.3@5671,-923
DISP0_CLK: J1.32
DISP0_CNTRST: J1.2
DISP0_DAT0: J1.26
DISP0_DAT1: J1.25
DISP0_DAT2: J1.24
DISP0_DAT3: J1.23
DISP0_DAT4: J1.22
DISP0_DAT5: J1.21
DISP0_DAT6: J1.20
DISP0_DAT7: J1.19
DISP0_DAT8: J1.18
DISP0_DAT9: J1.17
DISP0_DAT10: J1.16
DISP0_DAT11: J1.15
DISP0_DAT12: J1.14
DISP0_DAT13: J1.13
DISP0_DAT14: J1.12
DISP0_DAT15: J1.11
DISP0_DAT16: J1.10
DISP0_DAT17: J1.9
DISP0_DAT18: J1.8
DISP0_DAT19: J1.7
DISP0_DAT20: J1.6
DISP0_DAT21: J1.5
DISP0_DAT22: J1.4
DISP0_DAT23: J1.3
DISP0_DRDY: J1.30
DISP0_HSYNCH: J1.27
DISP0_VSYNCH: J1.28
EARTH: J3.BO1 J3.BO2 J5.15 J5.16 J6.BO1 J6.BO2 J7.9 J7.10 J7.11 J7.12 J8.9 J8.10 J8.11 J8.12 J9.6 J9.7 J9.8 J9.9 J10.10 J10.11 J10.12 J10.13 L3.2 P3.0 P4.0 P5.0 P7.0 P8.0 P9.0 pad.0@1850.39,-4094.49 pad.0@6023.62,0 pad.0@6023.62,-4094.49 | length 738.4
  Top Layer w80: J5.15@3630.88,-3718.08 3868.08,-3718.08 3910,-3760 3910,-3885
  Top Layer w85: J5.16@4231.12,-3723.08 4548.08,-3723.08
ECSPI1_CLK: J1.66
ECSPI1_CS1: J1.68
ECSPI1_MISO: J1.63
ECSPI1_MOSI: J1.61
ECSPI5_CLK: J1.72
ECSPI5_CS0: J1.70
ECSPI5_MISO: J1.65
ECSPI5_MOSI: J1.67
EIM_BCLK: J1.35
EIM_CS0: J1.55
EIM_CS1: J1.56
EIM_DA0: J1.54
EIM_DA1: J1.53
EIM_DA2: J1.52
EIM_DA3: J1.51
EIM_DA4: J1.50
EIM_DA5: J1.49
EIM_DA6: J1.48
EIM_DA7: J1.47
EIM_DA8: J1.46
EIM_DA9: J1.45
EIM_DA10: J1.44
EIM_DA11: J1.43
EIM_DA12: J1.42
EIM_DA13: J1.41
EIM_DA14: J1.40
EIM_DA15: J1.39
EIM_DATA0: J2.40
EIM_DATA1: J2.39
EIM_DATA2: J2.42
EIM_DATA3: J2.41
EIM_DATA4: J2.44
EIM_DATA5: J2.43
EIM_DATA6: J2.46
EIM_DATA7: J2.45
EIM_DATA8: J2.48
EIM_DATA9: J2.47
EIM_DATA10: J2.50
EIM_DATA11: J2.49
EIM_DATA12: J2.52
EIM_DATA13: J2.51
EIM_DATA14: J2.54
EIM_DATA15: J2.53
EIM_EB0: J1.64
EIM_EB1: J1.57
EIM_LBA: J1.62
EIM_OE: J1.58
EIM_RW: J1.60
EIM_WAIT: J1.37
GAIN: R49.1 R50.1 U10.8 | length 142.8
  Top Layer w10: R50.1@1118,-2494 1118,-2585 1132,-2599 U10.8@1132,-2631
